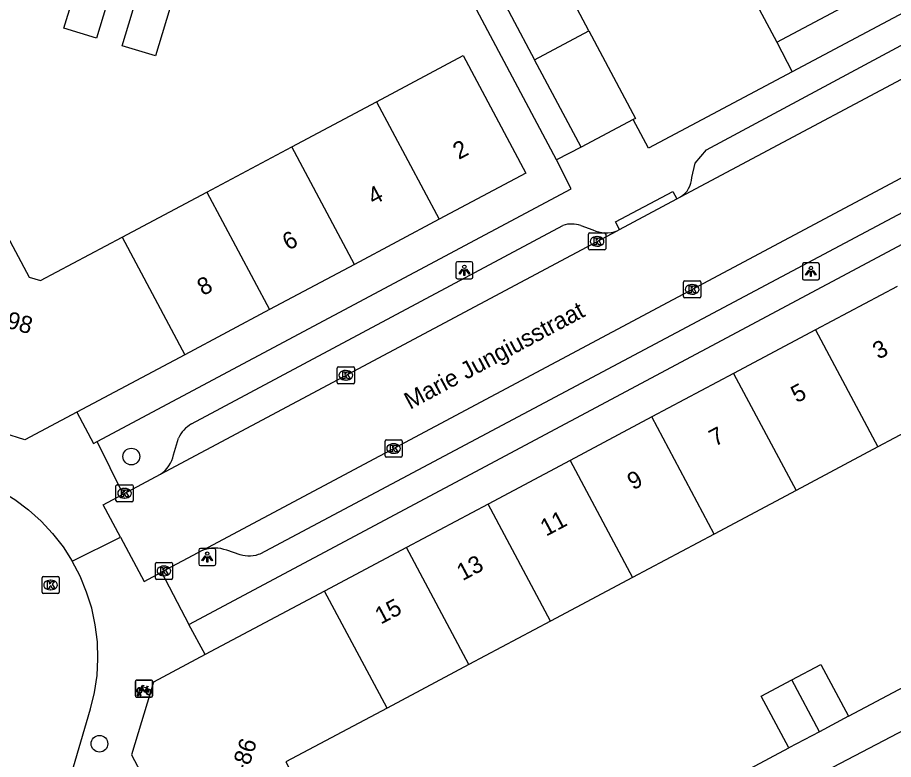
# Model space of a CAD drawing. Extents: x 160304 to 160954, y 383686 to 384161.
# Drawn here: x 160598.4 to 160649.6, y 383862.6 to 383906 of the extents above; entities that cross this region are included whole.
import ezdxf

# ---------------------------------------------------------------- set-up
doc = ezdxf.new("R2010")
doc.units = 0
for name, color, linetype in [('IMGEO_Boom', 7, 'Continuous'), ('IMGEO_Fietsenrek', 7, 'Continuous'), ('IMGEO_Kolk', 7, 'Continuous'), ('IMGEO_Lichtpunt', 7, 'Continuous'), ('IMGEO_Muur', 7, 'Continuous'), ('IMGEO_Openbare_ruimte_label', 7, 'Continuous'), ('IMGEO_Pand', 7, 'Continuous'), ('IMGEO_Pand_nummerreeks', 7, 'Continuous'), ('IMGEO_Rijbaan_lokaal_open', 7, 'Continuous'), ('IMGEO_Voetpad_open', 7, 'Continuous')]:
    doc.layers.add(name, color=color, linetype=linetype)

msp = doc.modelspace()

# ---------------------------------------------------------------- linework, layer by layer
at = {"layer": 'IMGEO_Boom'}
for centre in [(160605.02, 383880.291), (160603.156, 383863.502)]:
    msp.add_circle(centre, 0.489, dxfattribs=at)
at = {"layer": 'IMGEO_Fietsenrek'}
for p, q in [((160605.258, 383866.301), (160605.258, 383867.142)), ((160605.258, 383867.142), (160605.258, 383866.301)), ((160605.333, 383867.226), (160606.174, 383867.226)), ((160606.174, 383867.226), (160605.333, 383867.226)), ((160606.258, 383867.151), (160606.258, 383866.31)), ((160606.258, 383866.31), (160606.258, 383867.151)), ((160605.496, 383866.482), (160605.495, 383866.486)), ((160605.527, 383866.493), (160605.528, 383866.486)), ((160605.945, 383866.775), (160605.981, 383866.68)), ((160606.183, 383866.226), (160605.342, 383866.226)), ((160605.342, 383866.226), (160606.183, 383866.226)), ((160605.385, 383866.31), (160605.424, 383866.47)), ((160605.419, 383866.31), (160605.385, 383866.31)), ((160605.454, 383866.458), (160605.419, 383866.31)), ((160605.537, 383866.31), (160605.503, 383866.452)), ((160605.535, 383866.456), (160605.57, 383866.31)), ((160605.57, 383866.31), (160605.537, 383866.31))]:
    msp.add_line(p, q, dxfattribs=at)
for points in [[(160605.592, 383866.7), (160605.54, 383866.61), (160605.5, 383866.585), (160605.501, 383866.632), (160605.556, 383866.726)], [(160605.571, 383866.752), (160605.666, 383866.916), (160605.752, 383866.902), (160605.754, 383866.893), (160605.698, 383866.882), (160605.671, 383866.837), (160605.927, 383866.796)], [(160605.867, 383866.508), (160605.817, 383866.508), (160605.626, 383866.759), (160605.607, 383866.727)], [(160605.914, 383866.771), (160605.657, 383866.812), (160605.64, 383866.783), (160605.807, 383866.563), (160605.914, 383866.771)], [(160605.962, 383866.673), (160605.932, 383866.75), (160605.823, 383866.532), (160605.866, 383866.532)], [(160605.896, 383866.532), (160606.016, 383866.531), (160605.972, 383866.645)], [(160605.992, 383866.652), (160606.047, 383866.507), (160605.897, 383866.507)], [(160605.927, 383866.796), (160605.952, 383866.845), (160605.946, 383866.849), (160605.923, 383866.853), (160605.911, 383866.86), (160605.91, 383866.863), (160605.912, 383866.868), (160606.007, 383866.853), (160606.009, 383866.843), (160605.999, 383866.83), (160605.987, 383866.824), (160605.973, 383866.83), (160605.945, 383866.775)]]:
    msp.add_lwpolyline(points, dxfattribs=at)
for centre, radius, start, end in [((160605.336, 383867.148), 0.0779, 92.4484, 184.2845), ((160605.336, 383867.148), 0.0779, 92.4484, 184.2845), ((160606.18, 383867.148), 0.0779, 2.4484, 94.2845), ((160606.18, 383867.148), 0.0779, 2.4484, 94.2845), ((160605.498, 383866.611), 0.159, 62.6766, 242.1369), ((160605.498, 383866.611), 0.129, 63.3192, 238.903), ((160605.478, 383866.482), 0.0499, 12.8025, 158.6934), ((160605.478, 383866.482), 0.0174, 12.8025, 163.4502), ((160605.498, 383866.611), 0.129, 253.415, 269.0204), ((160605.498, 383866.611), 0.129, 283.6043, 43.4302), ((160605.498, 383866.611), 0.159, 283.5766, 46.6042), ((160606.025, 383866.527), 0.159, 113.3408, 178.3217), ((160606.025, 383866.527), 0.159, 187.0065, 105.7708), ((160606.025, 383866.527), 0.129, 113.923, 177.9556), ((160606.025, 383866.527), 0.129, 188.6715, 104.5883), ((160605.336, 383866.304), 0.0779, 182.4484, 274.2845), ((160605.336, 383866.304), 0.0779, 182.4484, 274.2845), ((160605.498, 383866.611), 0.159, 253.9967, 271.7867), ((160606.18, 383866.304), 0.0779, 272.4484, 4.2845), ((160606.18, 383866.304), 0.0779, 272.4484, 4.2845)]:
    msp.add_arc(centre, radius, start, end, dxfattribs=at)
at = {"layer": 'IMGEO_Kolk'}
for p, q in [((160631.735, 383892.446), (160631.735, 383893.298)), ((160631.81, 383893.372), (160632.662, 383893.372)), ((160632.223, 383893.152), (160632.248, 383893.152)), ((160632.736, 383893.298), (160632.736, 383892.446)), ((160632.246, 383892.592), (160632.221, 383892.592)), ((160632.662, 383892.372), (160631.81, 383892.372)), ((160637.363, 383890.566), (160638.215, 383890.566)), ((160637.288, 383889.64), (160637.288, 383890.492)), ((160637.776, 383890.346), (160637.801, 383890.346)), ((160638.289, 383890.492), (160638.289, 383889.64)), ((160638.215, 383889.566), (160637.363, 383889.566)), ((160637.799, 383889.786), (160637.774, 383889.786)), ((160617.053, 383884.617), (160617.053, 383885.469)), ((160617.128, 383885.543), (160617.98, 383885.543)), ((160618.054, 383885.469), (160618.054, 383884.617)), ((160617.541, 383885.323), (160617.566, 383885.323)), ((160617.98, 383884.543), (160617.128, 383884.543)), ((160617.564, 383884.763), (160617.539, 383884.763)), ((160619.844, 383880.336), (160619.844, 383881.188)), ((160619.919, 383881.262), (160620.771, 383881.262)), ((160620.332, 383881.042), (160620.357, 383881.042)), ((160620.845, 383881.188), (160620.845, 383880.336)), ((160620.355, 383880.482), (160620.33, 383880.482)), ((160620.771, 383880.262), (160619.919, 383880.262)), ((160604.122, 383877.72), (160604.122, 383878.572)), ((160604.197, 383878.646), (160605.049, 383878.646)), ((160604.61, 383878.426), (160604.635, 383878.426)), ((160605.123, 383878.572), (160605.123, 383877.72)), ((160604.633, 383877.866), (160604.608, 383877.866)), ((160605.049, 383877.646), (160604.197, 383877.646)), ((160606.424, 383873.178), (160606.424, 383874.03)), ((160606.499, 383874.104), (160607.351, 383874.104)), ((160606.912, 383873.884), (160606.937, 383873.884)), ((160607.425, 383874.03), (160607.425, 383873.178)), ((160599.803, 383872.354), (160599.803, 383873.206)), ((160599.878, 383873.28), (160600.73, 383873.28)), ((160600.804, 383873.206), (160600.804, 383872.354)), ((160606.935, 383873.324), (160606.91, 383873.324)), ((160600.291, 383873.06), (160600.316, 383873.06)), ((160607.351, 383873.104), (160606.499, 383873.104)), ((160600.73, 383872.28), (160599.878, 383872.28)), ((160600.314, 383872.5), (160600.289, 383872.5))]:
    msp.add_line(p, q, dxfattribs=at)
for points in [[(160631.735, 383892.446), (160631.735, 383893.298)], [(160631.81, 383893.372), (160632.662, 383893.372)], [(160632.736, 383893.298), (160632.736, 383892.446)], [(160632.056, 383893.072), (160632.179, 383893.072), (160632.179, 383892.921), (160632.309, 383893.072), (160632.473, 383893.072), (160632.327, 383892.921), (160632.48, 383892.672), (160632.328, 383892.672), (160632.243, 383892.836), (160632.179, 383892.769), (160632.179, 383892.672), (160632.056, 383892.672), (160632.056, 383893.072)], [(160632.662, 383892.372), (160631.81, 383892.372)], [(160637.363, 383890.566), (160638.215, 383890.566)], [(160637.288, 383889.64), (160637.288, 383890.492)], [(160637.609, 383890.266), (160637.732, 383890.266), (160637.732, 383890.115), (160637.862, 383890.266), (160638.026, 383890.266), (160637.88, 383890.115), (160638.033, 383889.866), (160637.881, 383889.866), (160637.796, 383890.03), (160637.732, 383889.963), (160637.732, 383889.866), (160637.609, 383889.866), (160637.609, 383890.266)], [(160638.289, 383890.492), (160638.289, 383889.64)], [(160638.215, 383889.566), (160637.363, 383889.566)], [(160617.053, 383884.617), (160617.053, 383885.469)], [(160617.128, 383885.543), (160617.98, 383885.543)], [(160618.054, 383885.469), (160618.054, 383884.617)], [(160617.374, 383885.243), (160617.497, 383885.243), (160617.497, 383885.092), (160617.627, 383885.243), (160617.791, 383885.243), (160617.645, 383885.092), (160617.798, 383884.843), (160617.646, 383884.843), (160617.561, 383885.007), (160617.497, 383884.94), (160617.497, 383884.843), (160617.374, 383884.843), (160617.374, 383885.243)], [(160617.98, 383884.543), (160617.128, 383884.543)], [(160619.844, 383880.336), (160619.844, 383881.188)], [(160619.919, 383881.262), (160620.771, 383881.262)], [(160620.165, 383880.962), (160620.288, 383880.962), (160620.288, 383880.811), (160620.418, 383880.962), (160620.582, 383880.962), (160620.436, 383880.811), (160620.589, 383880.562), (160620.437, 383880.562), (160620.352, 383880.726), (160620.288, 383880.659), (160620.288, 383880.562), (160620.165, 383880.562), (160620.165, 383880.962)], [(160620.845, 383881.188), (160620.845, 383880.336)], [(160620.771, 383880.262), (160619.919, 383880.262)], [(160604.122, 383877.72), (160604.122, 383878.572)], [(160604.197, 383878.646), (160605.049, 383878.646)], [(160604.443, 383878.346), (160604.566, 383878.346), (160604.566, 383878.195), (160604.696, 383878.346), (160604.86, 383878.346), (160604.714, 383878.195), (160604.867, 383877.946), (160604.715, 383877.946), (160604.63, 383878.11), (160604.566, 383878.043), (160604.566, 383877.946), (160604.443, 383877.946), (160604.443, 383878.346)], [(160605.123, 383878.572), (160605.123, 383877.72)], [(160605.049, 383877.646), (160604.197, 383877.646)], [(160606.424, 383873.178), (160606.424, 383874.03)], [(160606.499, 383874.104), (160607.351, 383874.104)], [(160606.745, 383873.804), (160606.868, 383873.804), (160606.868, 383873.653), (160606.998, 383873.804), (160607.162, 383873.804), (160607.016, 383873.653), (160607.169, 383873.404), (160607.017, 383873.404), (160606.932, 383873.568), (160606.868, 383873.501), (160606.868, 383873.404), (160606.745, 383873.404), (160606.745, 383873.804)], [(160607.425, 383874.03), (160607.425, 383873.178)], [(160599.803, 383872.354), (160599.803, 383873.206)], [(160599.878, 383873.28), (160600.73, 383873.28)], [(160600.804, 383873.206), (160600.804, 383872.354)], [(160600.124, 383872.98), (160600.247, 383872.98), (160600.247, 383872.829), (160600.377, 383872.98), (160600.541, 383872.98), (160600.395, 383872.829), (160600.548, 383872.58), (160600.396, 383872.58), (160600.311, 383872.744), (160600.247, 383872.677), (160600.247, 383872.58), (160600.124, 383872.58), (160600.124, 383872.98)], [(160607.351, 383873.104), (160606.499, 383873.104)], [(160600.73, 383872.28), (160599.878, 383872.28)]]:
    msp.add_lwpolyline(points, dxfattribs=at)
for centre, start, end in [((160631.812, 383893.296), 91.552, 178.448), ((160631.812, 383893.296), 91.552, 178.448), ((160632.66, 383893.296), 1.552, 88.448), ((160632.66, 383893.296), 1.552, 88.448), ((160631.812, 383892.448), 181.552, 268.448), ((160631.812, 383892.448), 181.552, 268.448), ((160632.66, 383892.448), 271.552, 358.448), ((160632.66, 383892.448), 271.552, 358.448), ((160637.365, 383890.49), 91.552, 178.448), ((160637.365, 383890.49), 91.552, 178.448), ((160638.213, 383890.49), 1.552, 88.448), ((160638.213, 383890.49), 1.552, 88.448), ((160637.365, 383889.642), 181.552, 268.448), ((160637.365, 383889.642), 181.552, 268.448), ((160638.213, 383889.642), 271.552, 358.448), ((160638.213, 383889.642), 271.552, 358.448), ((160617.13, 383885.467), 91.552, 178.448), ((160617.13, 383885.467), 91.552, 178.448), ((160617.978, 383885.467), 1.552, 88.448), ((160617.978, 383885.467), 1.552, 88.448), ((160617.13, 383884.619), 181.552, 268.448), ((160617.13, 383884.619), 181.552, 268.448), ((160617.978, 383884.619), 271.552, 358.448), ((160617.978, 383884.619), 271.552, 358.448), ((160619.921, 383881.186), 91.552, 178.448), ((160619.921, 383881.186), 91.552, 178.448), ((160620.769, 383881.186), 1.552, 88.448), ((160620.769, 383881.186), 1.552, 88.448), ((160619.921, 383880.338), 181.552, 268.448), ((160619.921, 383880.338), 181.552, 268.448), ((160620.769, 383880.338), 271.552, 358.448), ((160620.769, 383880.338), 271.552, 358.448), ((160604.199, 383878.57), 91.552, 178.448), ((160604.199, 383878.57), 91.552, 178.448), ((160605.047, 383878.57), 1.552, 88.448), ((160605.047, 383878.57), 1.552, 88.448), ((160604.199, 383877.722), 181.552, 268.448), ((160604.199, 383877.722), 181.552, 268.448), ((160605.047, 383877.722), 271.552, 358.448), ((160605.047, 383877.722), 271.552, 358.448), ((160606.501, 383874.028), 91.552, 178.448), ((160606.501, 383874.028), 91.552, 178.448), ((160607.349, 383874.028), 1.552, 88.448), ((160607.349, 383874.028), 1.552, 88.448), ((160599.88, 383873.204), 91.552, 178.448), ((160599.88, 383873.204), 91.552, 178.448), ((160600.728, 383873.204), 1.552, 88.448), ((160600.728, 383873.204), 1.552, 88.448), ((160606.501, 383873.18), 181.552, 268.448), ((160606.501, 383873.18), 181.552, 268.448), ((160607.349, 383873.18), 271.552, 358.448), ((160607.349, 383873.18), 271.552, 358.448), ((160599.88, 383872.356), 181.552, 268.448), ((160599.88, 383872.356), 181.552, 268.448), ((160600.728, 383872.356), 271.552, 358.448), ((160600.728, 383872.356), 271.552, 358.448)]:
    msp.add_arc(centre, 0.0765, start, end, dxfattribs=at)
for centre, major_axis, ratio, start_param, end_param in [((160632.222, 383892.872), (-0.387, 0.002), 0.722429, 4.712389, 7.853982), ((160632.247, 383892.872), (-0.39, 0.002), 0.717154, 1.570796, 4.712389), ((160637.775, 383890.066), (-0.387, 0.002), 0.722429, 4.712389, 7.853982), ((160637.8, 383890.066), (-0.39, 0.002), 0.717154, 1.570796, 4.712389), ((160617.54, 383885.043), (-0.387, 0.002), 0.722429, 4.712389, 7.853982), ((160617.565, 383885.043), (-0.39, 0.002), 0.717154, 1.570796, 4.712389), ((160620.331, 383880.762), (-0.387, 0.002), 0.722429, 4.712389, 7.853982), ((160620.356, 383880.762), (-0.39, 0.002), 0.717154, 1.570796, 4.712389), ((160604.609, 383878.146), (-0.387, 0.002), 0.722429, 4.712389, 7.853982), ((160604.634, 383878.146), (-0.39, 0.002), 0.717154, 1.570796, 4.712389), ((160606.911, 383873.604), (-0.387, 0.002), 0.722429, 4.712389, 7.853982), ((160606.936, 383873.604), (-0.39, 0.002), 0.717154, 1.570796, 4.712389), ((160600.29, 383872.78), (-0.387, 0.002), 0.722429, 4.712389, 7.853982), ((160600.315, 383872.78), (-0.39, 0.002), 0.717154, 1.570796, 4.712389)]:
    msp.add_ellipse(centre, major_axis=major_axis, ratio=ratio, start_param=start_param, end_param=end_param, dxfattribs=at)
at = {"layer": 'IMGEO_Lichtpunt'}
for p, q in [((160623.98, 383891.588), (160623.98, 383890.781)), ((160623.98, 383891.588), (160623.98, 383890.781)), ((160624.882, 383891.683), (160624.074, 383891.683)), ((160624.882, 383891.683), (160624.074, 383891.683)), ((160624.976, 383890.781), (160624.976, 383891.588)), ((160624.976, 383890.781), (160624.976, 383891.588)), ((160645.131, 383891.611), (160644.323, 383891.611)), ((160645.131, 383891.611), (160644.323, 383891.611)), ((160644.229, 383891.516), (160644.229, 383890.709)), ((160644.229, 383891.516), (160644.229, 383890.709)), ((160645.225, 383890.709), (160645.225, 383891.516)), ((160645.225, 383890.709), (160645.225, 383891.516)), ((160624.074, 383890.687), (160624.882, 383890.687)), ((160624.074, 383890.687), (160624.882, 383890.687)), ((160644.323, 383890.615), (160645.131, 383890.615)), ((160644.323, 383890.615), (160645.131, 383890.615)), ((160608.958, 383874.82), (160608.958, 383874.013)), ((160608.958, 383874.82), (160608.958, 383874.013)), ((160609.86, 383874.915), (160609.052, 383874.915)), ((160609.86, 383874.915), (160609.052, 383874.915)), ((160609.954, 383874.013), (160609.954, 383874.82)), ((160609.954, 383874.013), (160609.954, 383874.82)), ((160609.052, 383873.919), (160609.86, 383873.919)), ((160609.052, 383873.919), (160609.86, 383873.919))]:
    msp.add_line(p, q, dxfattribs=at)
for points in [[(160624.354, 383891.252), (160624.393, 383891.224), (160624.205, 383890.962), (160624.167, 383890.989), (160624.354, 383891.252)], [(160624.456, 383891.204), (160624.503, 383891.204), (160624.503, 383890.882), (160624.456, 383890.882), (160624.456, 383891.204)], [(160624.566, 383891.224), (160624.604, 383891.251), (160624.791, 383890.989), (160624.752, 383890.961), (160624.566, 383891.224)], [(160644.603, 383891.18), (160644.642, 383891.152), (160644.454, 383890.89), (160644.416, 383890.917), (160644.603, 383891.18)], [(160644.705, 383891.132), (160644.752, 383891.132), (160644.752, 383890.81), (160644.705, 383890.81), (160644.705, 383891.132)], [(160644.815, 383891.152), (160644.853, 383891.179), (160645.04, 383890.917), (160645.001, 383890.889), (160644.815, 383891.152)], [(160609.332, 383874.484), (160609.371, 383874.456), (160609.183, 383874.194), (160609.145, 383874.221), (160609.332, 383874.484)], [(160609.434, 383874.436), (160609.481, 383874.436), (160609.481, 383874.114), (160609.434, 383874.114), (160609.434, 383874.436)], [(160609.544, 383874.456), (160609.582, 383874.483), (160609.769, 383874.221), (160609.73, 383874.193), (160609.544, 383874.456)]]:
    msp.add_lwpolyline(points, dxfattribs=at)
for centre in [(160624.479, 383891.386), (160644.728, 383891.314), (160609.457, 383874.618)]:
    msp.add_circle(centre, 0.0994, dxfattribs=at)
for centre, start, end in [((160624.074, 383891.588), 90, 180), ((160624.074, 383891.588), 90, 180), ((160624.882, 383891.588), 0, 90), ((160624.882, 383891.588), 0, 90), ((160644.323, 383891.516), 90, 180), ((160644.323, 383891.516), 90, 180), ((160645.131, 383891.516), 0, 90), ((160645.131, 383891.516), 0, 90), ((160624.074, 383890.781), 180, 270), ((160624.074, 383890.781), 180, 270), ((160624.882, 383890.781), 270, 0), ((160624.882, 383890.781), 270, 360), ((160644.323, 383890.709), 180, 270), ((160644.323, 383890.709), 180, 270), ((160645.131, 383890.709), 270, 0), ((160645.131, 383890.709), 270, 360), ((160609.052, 383874.82), 90, 180), ((160609.052, 383874.82), 90, 180), ((160609.86, 383874.82), 0, 90), ((160609.86, 383874.82), 0, 90), ((160609.052, 383874.013), 180, 270), ((160609.052, 383874.013), 180, 270), ((160609.86, 383874.013), 270, 0), ((160609.86, 383874.013), 270, 360)]:
    msp.add_arc(centre, 0.0946, start, end, dxfattribs=at)
at = {"layer": 'IMGEO_Muur'}
for points in [[(160642.729, 383904.527), (160643.629, 383902.793)], [(160643.629, 383902.793), (160635.231, 383898.324), (160634.341, 383899.993)]]:
    msp.add_lwpolyline(points, dxfattribs=at)
at = {"layer": 'IMGEO_Pand'}
for points in [[(160640.012, 383909.64), (160640.385, 383908.944), (160642.729, 383904.527), (160650.045, 383908.409), (160647.339, 383913.508)], [(160631.757, 383905.183), (160629.058, 383910.27)], [(160602.12, 383908.768), (160604.025, 383908.193), (160602.987, 383904.756), (160601.082, 383905.331), (160602.12, 383908.768)], [(160625.88, 383908.582), (160628.579, 383903.496)], [(160605.518, 383907.742), (160607.471, 383907.152), (160606.433, 383903.715), (160604.48, 383904.305), (160605.518, 383907.742)], [(160628.579, 383903.496), (160631.757, 383905.183)], [(160631.757, 383905.183), (160634.474, 383900.063), (160634.341, 383899.993)], [(160619.346, 383901.038), (160624.41, 383903.736), (160628.072, 383896.861), (160623.008, 383894.164)], [(160631.296, 383898.376), (160628.579, 383903.496)], [(160614.39, 383898.398), (160619.346, 383901.038)], [(160619.346, 383901.038), (160623.008, 383894.164)], [(160634.341, 383899.993), (160631.296, 383898.376)], [(160609.434, 383895.758), (160614.39, 383898.398)], [(160618.052, 383891.524), (160614.39, 383898.398)], [(160604.477, 383893.118), (160609.434, 383895.758)], [(160609.434, 383895.758), (160613.096, 383888.884)], [(160623.008, 383894.164), (160618.052, 383891.524)], [(160597.603, 383893.497), (160599.049, 383890.783), (160599.714, 383890.581), (160604.477, 383893.118)], [(160604.477, 383893.118), (160608.139, 383886.243)], [(160618.052, 383891.524), (160613.096, 383888.884)], [(160649.769, 383890.243), (160644.989, 383887.698)], [(160613.096, 383888.884), (160608.139, 383886.243)], [(160644.989, 383887.698), (160640.21, 383885.153)], [(160644.989, 383887.698), (160648.636, 383880.851)], [(160608.139, 383886.243), (160601.831, 383882.883)], [(160601.831, 383882.883), (160598.806, 383881.272), (160597.563, 383881.652), (160595.841, 383882.177), (160594.706, 383882.522), (160593.071, 383885.591)], [(160640.21, 383885.153), (160635.431, 383882.608)], [(160640.21, 383885.153), (160643.857, 383878.306)], [(160653.415, 383883.396), (160648.636, 383880.851)], [(160635.431, 383882.608), (160630.652, 383880.062)], [(160639.077, 383875.76), (160635.431, 383882.608)], [(160648.636, 383880.851), (160643.857, 383878.306)], [(160630.652, 383880.062), (160625.873, 383877.517)], [(160630.652, 383880.062), (160634.299, 383873.215)], [(160643.857, 383878.306), (160639.077, 383875.76)], [(160625.873, 383877.517), (160621.093, 383874.972)], [(160629.519, 383870.669), (160625.873, 383877.517)], [(160639.077, 383875.76), (160634.299, 383873.215)], [(160621.093, 383874.972), (160616.314, 383872.427)], [(160624.74, 383868.124), (160621.093, 383874.972)], [(160634.299, 383873.215), (160629.519, 383870.669)], [(160616.314, 383872.427), (160609.342, 383868.714)], [(160619.961, 383865.579), (160616.314, 383872.427)], [(160629.519, 383870.669), (160624.74, 383868.124)], [(160609.342, 383868.714), (160606.323, 383867.106), (160605.944, 383865.863), (160605.42, 383864.141), (160605.024, 383862.845), (160606.586, 383859.913)], [(160624.74, 383868.124), (160619.961, 383865.579)], [(160643.615, 383867.237), (160645.299, 383868.133), (160646.918, 383865.106)], [(160643.442, 383863.255), (160641.822, 383866.283), (160643.615, 383867.237)], [(160645.228, 383864.206), (160643.615, 383867.237)], [(160619.961, 383865.579), (160614.056, 383862.434), (160616.932, 383857.033)], [(160646.918, 383865.106), (160645.228, 383864.206)], [(160645.228, 383864.206), (160643.442, 383863.255)]]:
    msp.add_lwpolyline(points, dxfattribs=at)
at = {"layer": 'IMGEO_Rijbaan_lokaal_open'}
for points in [[(160637.105, 383895.469), (160654.821, 383904.917)], [(160609.197, 383874.818), (160660.608, 383902.238)], [(160633.542, 383893.569), (160636.895, 383895.357)], [(160636.895, 383895.357), (160637.105, 383895.469)], [(160606.718, 383879.264), (160633.401, 383893.494)], [(160633.401, 383893.494), (160633.542, 383893.569)], [(160587.654, 383882.722), (160587.681, 383882.688), (160588.086, 383882.269), (160588.526, 383881.888), (160588.999, 383881.548), (160589.501, 383881.251), (160590.026, 383881.001), (160590.253, 383880.91), (160595.731, 383879.039), (160596.473, 383878.741), (160597.361, 383878.297), (160598.207, 383877.776), (160599.003, 383877.181), (160599.742, 383876.518), (160600.42, 383875.791), (160601.029, 383875.006), (160601.566, 383874.171)], [(160604.537, 383878.101), (160606.718, 383879.264)], [(160604.38, 383875.585), (160603.369, 383877.478), (160604.496, 383878.079), (160604.537, 383878.101)], [(160604.38, 383875.585), (160605.766, 383872.988), (160606.789, 383873.534)], [(160609.197, 383874.818), (160606.789, 383873.534)], [(160614.718, 383831.355), (160607.23, 383845.532), (160601.204, 383856.942), (160601.168, 383857.1), (160601.049, 383857.809), (160600.993, 383858.527), (160601.001, 383859.246), (160601.074, 383859.962), (160601.21, 383860.668), (160601.409, 383861.36), (160602.642, 383865.533), (160602.872, 383866.499), (160603.015, 383867.482), (160603.07, 383868.474), (160603.036, 383869.467), (160602.913, 383870.453), (160602.702, 383871.424), (160602.406, 383872.372), (160602.026, 383873.29), (160601.566, 383874.171)]]:
    msp.add_lwpolyline(points, dxfattribs=at)
at = {"layer": 'IMGEO_Voetpad_open'}
for points in [[(160629.871, 383897.643), (160619.737, 383916.693)], [(160653.56, 383908.079), (160643.629, 383902.793), (160635.231, 383898.324), (160634.341, 383899.993)], [(160637.769, 383896.609), (160637.96, 383897.447), (160638.621, 383898.233), (160651.578, 383905.192)], [(160659.026, 383899.322), (160612.533, 383874.592), (160612.437, 383874.556), (160612.289, 383874.513), (160612.138, 383874.484), (160611.985, 383874.468), (160611.832, 383874.466), (160611.678, 383874.478), (160611.527, 383874.503), (160611.378, 383874.542), (160610.603, 383874.809), (160610.429, 383874.865), (160610.25, 383874.906), (160610.069, 383874.93), (160609.886, 383874.938), (160609.703, 383874.93), (160609.522, 383874.905), (160609.343, 383874.864), (160609.197, 383874.818)], [(160608.385, 383870.479), (160660.662, 383898.369), (160661.53, 383896.507)], [(160631.296, 383898.376), (160629.871, 383897.643)], [(160603.019, 383881.171), (160630.716, 383895.952), (160629.871, 383897.643)], [(160633.542, 383893.569), (160633.308, 383894.01), (160636.661, 383895.798), (160636.895, 383895.357)], [(160608.541, 383882.199), (160630.237, 383893.81)], [(160631.279, 383893.796), (160631.989, 383893.542)], [(160601.831, 383882.883), (160602.81, 383881.06), (160603.019, 383881.171)], [(160607.485, 383880.384), (160607.766, 383881.362)], [(160604.537, 383878.101), (160603.019, 383881.171)], [(160601.566, 383874.171), (160604.38, 383875.585)], [(160606.789, 383873.534), (160608.385, 383870.479)], [(160609.342, 383868.714), (160608.385, 383870.479)], [(160646.918, 383865.106), (160650.194, 383866.852), (160652.219, 383866.231)], [(160660.368, 383855.882), (160663.366, 383857.479), (160661.32, 383861.3), (160658.581, 383862.138), (160650.651, 383864.543), (160645.18, 383861.678), (160647.154, 383857.81)], [(160639.506, 383859.586), (160640.057, 383861.451), (160643.442, 383863.255)]]:
    msp.add_lwpolyline(points, dxfattribs=at)
for centre, radius, start, end in [((160636.397, 383896.645), 1.372, 301.0505, 358.5117), ((160630.737, 383892.249), 1.639, 70.6986, 107.7619), ((160632.752, 383895.189), 1.815, 245.1516, 290.9544), ((160609.417, 383880.61), 1.814, 118.8779, 155.5273), ((160605.709, 383880.778), 1.82, 303.6933, 347.4983)]:
    msp.add_arc(centre, radius, start, end, dxfattribs=at)

# ---------------------------------------------------------------- texts
at = {"layer": 'IMGEO_Openbare_ruimte_label'}
msp.add_text('Marie Jungiusstraat', height=1, rotation=28.1028, dxfattribs=at).set_placement((160621.307, 383883.022))
at = {"layer": 'IMGEO_Pand_nummerreeks'}
for s, rotation, p in [('2', 28.0435, (160624.151, 383897.627)), ('4', 28.0435, (160619.17, 383894.974)), ('6', 28.0435, (160614.186, 383892.319)), ('8', 28.0435, (160609.206, 383889.667)), ('88-98', 344.2207, (160595.792, 383888.369)), ('3', 28.0369, (160648.678, 383885.946)), ('5', 28.0369, (160643.899, 383883.401)), ('7', 28.0369, (160639.12, 383880.855)), ('9', 28.0369, (160634.34, 383878.31)), ('11', 28.0369, (160629.255, 383875.602)), ('13', 28.0369, (160624.376, 383873.004)), ('15', 28.0369, (160619.597, 383870.459)), ('76-86', 72.2156, (160611.328, 383860.355))]:
    msp.add_text(s, height=1, rotation=rotation, dxfattribs=at).set_placement(p)

doc.saveas('drawing.dxf')
